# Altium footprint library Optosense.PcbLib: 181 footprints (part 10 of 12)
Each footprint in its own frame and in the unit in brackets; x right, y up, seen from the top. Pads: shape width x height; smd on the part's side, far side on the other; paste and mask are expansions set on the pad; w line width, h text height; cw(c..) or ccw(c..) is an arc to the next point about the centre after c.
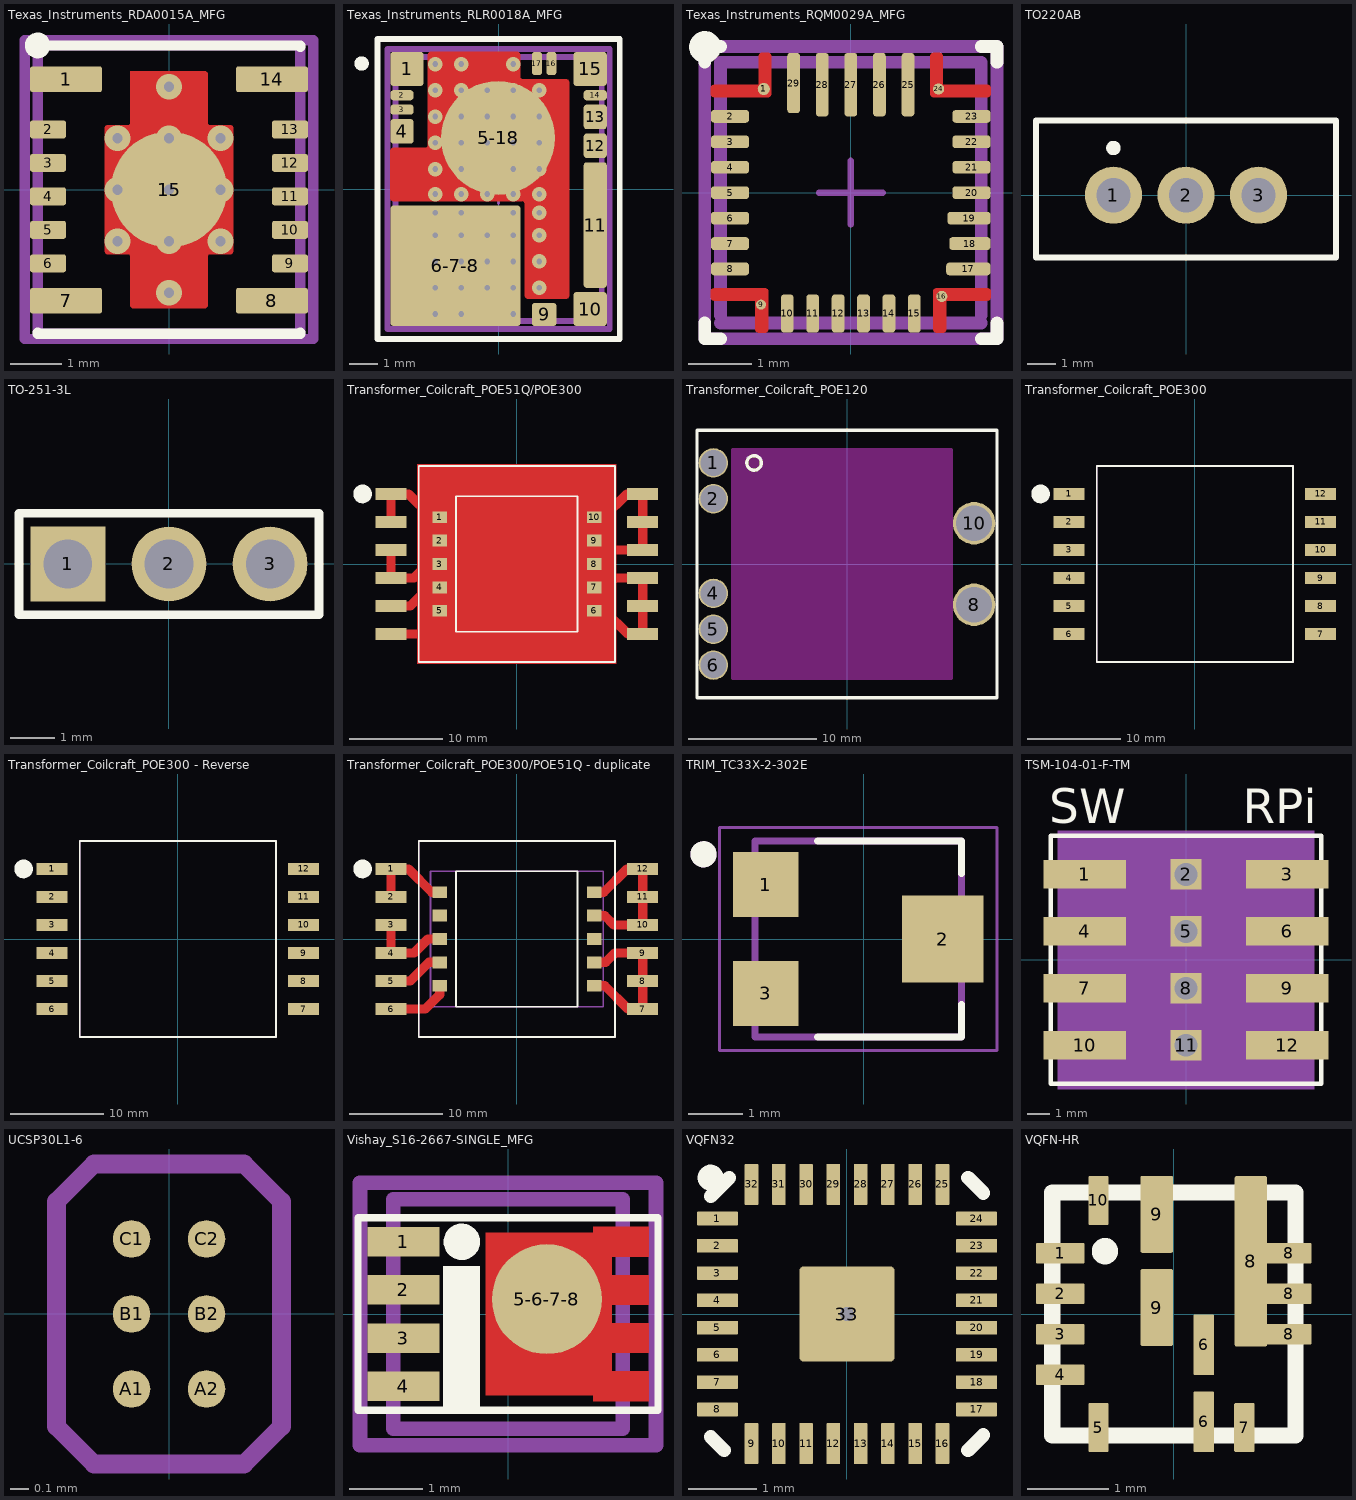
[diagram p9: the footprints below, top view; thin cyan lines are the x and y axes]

## Texas_Instruments_RDA0015A_MFG [mm]
pads (15):
  rrect20% 1.4x0.5 smd paste-1000 mask+0: 1(-2,2.145) 7(-2,-2.155) 8(2,-2.155) 14(2,2.145)
  rrect29% 0.7x0.35 smd paste-1000 mask+0: 2(-2.35,1.17) 3(-2.35,0.52) 4(-2.35,-0.13) 5(-2.35,-0.78) 6(-2.35,-1.43) 9(2.35,-1.43) 10(2.35,-0.78) 11(2.35,-0.13) 12(2.35,0.52) 13(2.35,1.17)
  round 2.25 smd paste-1000 mask+0: 15(0,0)
via 0,2 diameter 0.5 hole 0.2
via 0,1 diameter 0.5 hole 0.2
via 0,0 diameter 0.5 hole 0.2
via 0,-1 diameter 0.5 hole 0.2
via 0,-2 diameter 0.5 hole 0.2
via -1,1 diameter 0.5 hole 0.2
via -1,0 diameter 0.5 hole 0.2
via -1,-1 diameter 0.5 hole 0.2
via 1,1 diameter 0.5 hole 0.2
via 1,0 diameter 0.5 hole 0.2
via 1,-1 diameter 0.5 hole 0.2
Top Layer:
  region: -0.75,2.3 -0.753,2.294 -0.757,2.282 -0.757,2.268 -0.753,2.256 -0.75,2.25 -0.75,1.3 -0.751,1.29 -0.758,1.272 -0.772,1.258 -0.79,1.251 -0.8,1.25 -1.2,1.25 -1.21,1.25 -1.228,1.242 -1.242,1.228 -1.25,1.21 -1.25,1.2 -1.25,-1.2 -1.25,-1.21 -1.242,-1.228 -1.228,-1.242 -1.21,-1.25 -1.2,-1.25 -0.8,-1.25 -0.79,-1.251 -0.772,-1.258 -0.758,-1.272 -0.751,-1.29 -0.75,-1.3 -0.75,-2.25 -0.75,-2.26 -0.742,-2.278 -0.728,-2.292 -0.71,-2.3 -0.7,-2.3 0.7,-2.3 0.71,-2.3 0.728,-2.292 0.742,-2.278 0.75,-2.26 0.75,-2.25 0.75,-1.3 0.751,-1.29 0.758,-1.272 0.772,-1.258 0.79,-1.251 0.8,-1.25 1.2,-1.25 1.21,-1.25 1.228,-1.242 1.242,-1.228 1.25,-1.21 1.25,-1.2 1.25,1.2 1.25,1.21 1.242,1.228 1.228,1.242 1.21,1.25 1.2,1.25 0.8,1.25 0.79,1.251 0.772,1.258 0.758,1.272 0.751,1.29 0.75,1.3 0.75,2.25 0.75,2.26 0.742,2.278 0.728,2.292 0.71,2.3 0.7,2.3
Top Overlay:
  circle w0.25: c-2.551,2.802 r0.125
  lines w0.2: -2.55,-2.78 -2.55,-2.8 2.55,-2.8 2.55,-2.78 ; -2.55,2.77 -2.55,2.8 2.55,2.8 2.55,2.77
Top Paste:
  drawing of 22 lines, arcs and shapes, not listed
Mechanical 10:
  lines w0.2: -2.8,-2.9 2.8,-2.9 2.8,2.9 -2.8,2.9 -2.8,-2.9
  text ".Designator" at 0,0 h1
Mechanical 12:
  lines w0.2: -2.55,-2.8 2.55,-2.8 2.55,2.8 -2.55,2.8 -2.55,-2.8
Mechanical 15:
  lines w0.1: -0.5,0 0.5,0 ; 0,-0.5 0,0.5
  lines w0.2: -2.8,-2.9 2.8,-2.9 2.8,2.9 -2.8,2.9 -2.8,-2.9
3D body "IC_Texas_Instruments_TPSM53604RDAR_eec.STEP": height 0.25, standoff 0, extent -2.8,-2.9 2.8,2.9

## Texas_Instruments_RLR0018A_MFG [mm]
pads (15):
  rrect17% 1.15x1.175 smd paste-1000 mask-1000: 1(-3.176,4.163) 10(3.176,-4.163) 15(3.176,4.163)
  rrect57% 0.8x0.35 smd paste-1000 mask-1000: 2(-3.35,3.25) 3(-3.35,2.75) 14(3.35,3.25)
  rrect25% 0.8x0.85 smd paste-1000 mask-1000: 4(-3.35,2) 12(3.35,1.5) 13(3.35,2.5)
  round 3.952 smd paste-1000 mask-1000: 5-18(-0.021,1.771)
  rrect5% 4.51x4.176 smd paste-1000 mask-1000: 6-7-8(-1.495,-2.663)
  rrect25% 0.85x0.8 smd paste-1000 mask-1000: 9(1.58,-4.35)
  rrect25% 0.8x4.35 smd paste-1000 mask-1000: 11(3.35,-1.25)
  rrect57% 0.35x0.8 smd paste-1000 mask-1000: 16(1.83,4.35) 17(1.33,4.35)
via -2.195,4.33 diameter 0.5 hole 0.2
via -1.295,4.33 diameter 0.5 hole 0.2
via 0.505,4.33 diameter 0.5 hole 0.2
via -2.195,1.6 diameter 0.5 hole 0.2
via -1.295,1.6 diameter 0.5 hole 0.2
via -0.395,1.6 diameter 0.5 hole 0.2
via 0.505,1.6 diameter 0.5 hole 0.2
via 1.405,1.6 diameter 0.5 hole 0.2
via -2.195,0.69 diameter 0.5 hole 0.2
via -1.295,0.69 diameter 0.5 hole 0.2
via 0.505,0.69 diameter 0.5 hole 0.2
via 1.405,0.69 diameter 0.5 hole 0.2
via -2.195,-0.175 diameter 0.5 hole 0.2
via -1.295,-0.175 diameter 0.5 hole 0.2
via -0.395,-0.175 diameter 0.5 hole 0.2
via 0.505,-0.175 diameter 0.5 hole 0.2
via 1.405,-0.175 diameter 0.5 hole 0.2
via -2.195,-0.825 diameter 0.5 hole 0.2
via -1.295,-0.825 diameter 0.5 hole 0.2
via 0.505,-0.825 diameter 0.5 hole 0.2
via 1.405,-0.825 diameter 0.5 hole 0.2
via -2.195,-1.6 diameter 0.5 hole 0.2
via -1.295,-1.6 diameter 0.5 hole 0.2
via -0.395,-1.6 diameter 0.5 hole 0.2
via 0.505,-1.6 diameter 0.5 hole 0.2
via 1.405,-1.6 diameter 0.5 hole 0.2
via -2.195,-2.51 diameter 0.5 hole 0.2
via -1.295,-2.51 diameter 0.5 hole 0.2
via -0.395,-2.51 diameter 0.5 hole 0.2
via 0.505,-2.51 diameter 0.5 hole 0.2
via 1.405,-2.51 diameter 0.5 hole 0.2
via -2.195,-3.42 diameter 0.5 hole 0.2
via -1.295,-3.42 diameter 0.5 hole 0.2
via -0.395,-3.42 diameter 0.5 hole 0.2
via 0.505,-3.42 diameter 0.5 hole 0.2
via 1.405,-3.42 diameter 0.5 hole 0.2
via -2.195,-4.33 diameter 0.5 hole 0.2
via -1.295,-4.33 diameter 0.5 hole 0.2
via 0.505,-4.33 diameter 0.5 hole 0.2
via -2.195,2.51 diameter 0.5 hole 0.2
via -1.295,2.51 diameter 0.5 hole 0.2
via -0.395,2.51 diameter 0.5 hole 0.2
via 0.505,2.51 diameter 0.5 hole 0.2
via 1.405,2.51 diameter 0.5 hole 0.2
via -2.195,3.42 diameter 0.5 hole 0.2
via -1.295,3.42 diameter 0.5 hole 0.2
via -0.395,3.42 diameter 0.5 hole 0.2
via 0.505,3.42 diameter 0.5 hole 0.2
via 1.405,3.42 diameter 0.5 hole 0.2
Top Layer:
  region: -3.651,1.425 -2.551,1.425 -2.531,1.427 -2.495,1.442 -2.467,1.47 -2.452,1.506 -2.451,1.525 -2.45,4.651 -2.45,4.67 -2.435,4.707 -2.407,4.735 -2.37,4.751 -2.35,4.751 -2.351,4.751 0.65,4.751 0.67,4.751 0.707,4.735 0.735,4.707 0.75,4.67 0.75,4.651 0.75,3.9 0.752,3.88 0.767,3.844 0.794,3.817 0.83,3.802 0.85,3.8 2.35,3.8 2.37,3.8 2.407,3.785 2.435,3.757 2.45,3.72 2.45,3.7 2.45,-3.7 2.45,-3.72 2.435,-3.757 2.407,-3.785 2.37,-3.8 2.35,-3.8 1.01,-3.8 0.99,-3.8 0.953,-3.785 0.925,-3.757 0.91,-3.72 0.91,-3.7 0.91,-0.525 0.908,-0.505 0.893,-0.469 0.866,-0.442 0.83,-0.427 0.81,-0.425 -3.65,-0.425 -3.67,-0.425 -3.707,-0.41 -3.735,-0.382 -3.75,-0.345 -3.75,-0.325 -3.751,-0.325 -3.75,1.325 -3.75,1.345 -3.735,1.382 -3.707,1.41 -3.67,1.425
Top Overlay:
  circle w0.25: c-4.75,4.351 r0.125
  lines w0.2: -4.2,-5.2 4.2,-5.2 4.2,5.2 -4.2,5.2 -4.2,-5.2
Top Paste:
  drawing of 46 lines, arcs and shapes, not listed
Top Solder:
  drawing of 18 lines, arcs and shapes, not listed
Mechanical 10:
  lines w0.2: -3.851,-4.851 3.851,-4.851 3.851,4.851 -3.851,4.851 -3.851,-4.851
  text ".Designator" at 0,0 h1
Mechanical 12:
  lines w0.2: -3.575,-4.575 3.575,-4.575 3.575,4.575 -3.575,4.575 -3.575,-4.575
Mechanical 15:
  lines w0.1: -0.5,0 0.5,0 ; 0,-0.5 0,0.5
  lines w0.2: -3.851,-4.851 3.851,-4.851 3.851,4.851 -3.851,4.851 -3.851,-4.851
3D body "IC_Texas_Instruments_LMZM33603RLRR_eec.STEP": height 0.25, standoff 0, extent -3.851,-4.851 3.851,4.851

## Texas_Instruments_RQM0029A_MFG [mm]
pads (29):
  round 0.192 smd paste-0.025 mask+0: 1(-1.369,1.631)
  rrect50% 0.6x0.2 smd paste-0.025 mask+0: 2(-1.9,1.2) 3(-1.9,0.8) 4(-1.9,0.4) 5(-1.9,0) 6(-1.9,-0.4) 7(-1.9,-0.8) 8(-1.9,-1.2) 20(1.9,0) 21(1.9,0.4) 22(1.9,0.8) 23(1.9,1.2)
  round 0.158 smd paste-0.025 mask+0: 9(-1.412,-1.763)
  rrect50% 0.2x0.6 smd paste-0.025 mask+0: 10(-1,-1.9) 11(-0.6,-1.9) 12(-0.2,-1.9) 13(0.2,-1.9) 14(0.6,-1.9) 15(1,-1.9)
  round 0.175 smd paste-0.025 mask+0: 16(1.431,-1.631) 24(1.381,1.631)
  rrect50% 0.7x0.2 smd paste-0.025 mask+0: 17(1.85,-1.2)
  rrect50% 0.65x0.2 smd paste-0.025 mask+0: 18(1.875,-0.8)
  rrect50% 0.68x0.2 smd paste-0.025 mask+0: 19(1.86,-0.4)
  rrect50% 0.2x1 smd paste-0.025 mask+0: 25(0.9,1.7) 26(0.45,1.7) 27(0,1.7) 28(-0.45,1.7)
  rrect50% 0.2x0.95 smd paste-0.025 mask+0: 29(-0.9,1.725)
Top Layer:
  region: 2.2,1.65 2.2,1.66 2.192,1.678 2.178,1.692 2.16,1.7 2.15,1.7 1.45,1.7 1.45,2.15 1.45,2.16 1.442,2.178 1.428,2.192 1.41,2.2 1.4,2.2 1.3,2.2 1.29,2.2 1.272,2.192 1.258,2.178 1.25,2.16 1.25,2.15 1.25,1.55 1.25,1.54 1.258,1.522 1.272,1.508 1.29,1.5 1.3,1.5 2.15,1.5 2.16,1.5 2.178,1.508 2.192,1.522 2.2,1.54 2.2,1.55
  region: 2.2,-1.65 2.2,-1.66 2.192,-1.678 2.178,-1.692 2.16,-1.7 2.15,-1.7 1.5,-1.7 1.5,-2.15 1.5,-2.16 1.492,-2.178 1.478,-2.192 1.46,-2.2 1.45,-2.2 1.35,-2.2 1.34,-2.2 1.322,-2.192 1.308,-2.178 1.3,-2.16 1.3,-2.15 1.3,-1.55 1.3,-1.54 1.308,-1.522 1.322,-1.508 1.34,-1.5 1.35,-1.5 2.15,-1.5 2.16,-1.5 2.178,-1.508 2.192,-1.522 2.2,-1.54 2.2,-1.55
  region: -2.2,-1.65 -2.2,-1.66 -2.192,-1.678 -2.178,-1.692 -2.16,-1.7 -2.15,-1.7 -1.5,-1.7 -1.5,-2.15 -1.5,-2.16 -1.492,-2.178 -1.478,-2.192 -1.46,-2.2 -1.45,-2.2 -1.35,-2.2 -1.34,-2.2 -1.322,-2.192 -1.308,-2.178 -1.3,-2.16 -1.3,-2.15 -1.3,-1.55 -1.3,-1.54 -1.308,-1.522 -1.322,-1.508 -1.34,-1.5 -1.35,-1.5 -2.15,-1.5 -2.16,-1.5 -2.178,-1.508 -2.192,-1.522 -2.2,-1.54 -2.2,-1.55
  region: -2.2,1.65 -2.2,1.66 -2.192,1.678 -2.178,1.692 -2.16,1.7 -2.15,1.7 -1.45,1.7 -1.45,2.15 -1.45,2.16 -1.442,2.178 -1.428,2.192 -1.41,2.2 -1.4,2.2 -1.3,2.2 -1.29,2.2 -1.272,2.192 -1.258,2.178 -1.25,2.16 -1.25,2.15 -1.25,1.55 -1.25,1.54 -1.258,1.522 -1.272,1.508 -1.29,1.5 -1.3,1.5 -2.15,1.5 -2.16,1.5 -2.178,1.508 -2.192,1.522 -2.2,1.54 -2.2,1.55
Top Overlay:
  circle w0.25: c-2.295,2.291 r0.125
  lines w0.2: -2.3,-2.05 -2.3,-2.3 -2.05,-2.3 ; -2.3,2.05 -2.3,2.3 -2.05,2.3 ; 2.05,-2.3 2.3,-2.3 2.3,-2.05 ; 2.05,2.3 2.3,2.3 2.3,2.05
Mechanical 10:
  lines w0.2: -2.3,-2.3 -2.3,2.3 2.3,2.3 2.3,-2.3 -2.3,-2.3
  text ".Designator" at 0,0.188 h1
Mechanical 12:
  lines w0.2: -2.05,-2.05 2.05,-2.05 ; -2.05,-1.93 -2.05,2.05 2.05,2.05 2.05,-1.93
Mechanical 15:
  lines w0.1: -0.5,0 0.5,0 ; 0,-0.5 0,0.5
  lines w0.2: -2.3,-2.3 -2.3,2.3 2.3,2.3 2.3,-2.3 -2.3,-2.3
3D body "IC_Texas_Instruments_BQ25792RQMR_eec.STEP": height 0.25, standoff 0, extent -2.3,-2.3 2.3,2.3

## TO220AB [mm]
height 19.6
pads (3):
  round 2 hole 1.2: 1(-2.54,0) 2(0,0) 3(2.54,0)
Top Overlay:
  circle w0.254: c-2.54,1.65 r0.125
  lines w0.2: -5.25,-2.184 5.25,-2.184 5.25,2.616 -5.25,2.616 -5.25,-2.184
3D body "User Library-TO-220AB.STEP": height 20.86, standoff -3, extent -5.31,-2.214 5.36,2.616

## TO-251-3L [mm]
pads (3):
  rect 1.7x1.7 hole 1.1: 1(-2.29,0)
  round 1.7 hole 1.1: 2(0,0) 3(2.29,0)
Top Overlay:
  lines w0.2: -3.4,-1.15 -3.4,1.15 3.4,1.15 3.4,-1.15 -3.4,-1.15

## Transformer_Coilcraft_POE51Q/POE300 [mm] "POE300F-24L"
height 9.652
pads (23):
  rect 1.55x1.27 smd: 1(-8.268,5) 2(-8.268,2.5) 3(-8.268,0) 4(-8.268,-2.5) 5(-8.268,-5) 6(8.268,-5) 7(8.268,-2.5) 8(8.268,0) 9(8.268,2.5) 10(8.268,5)
  rect 3.3x1.27 smd: ""(-13.46,-7.5) ""(-13.46,-4.5) ""(-13.46,-1.5) ""(-13.46,1.5) ""(-13.46,4.5) ""(-13.46,7.5) ""(-13.46,7.5) ""(13.46,-7.5) ""(13.46,-4.5) ""(13.46,-1.5) ""(13.46,1.5) ""(13.46,4.5) ""(13.46,7.5)
Top Layer:
  pour cut-out: -10.668,10.668 -10.668,-10.668 10.668,-10.668 10.668,10.668
  lines w0.254: -13.46,4.5 -13.46,7.5 -11.3,7.5 -8.8,5 ; -9.1,5 -8.268,5 ; 8.268,5 8.8,5
  lines w1: -13.46,-7.5 -9.8,-7.5 -8.268,-5.968 -8.268,-5 ; -13.46,-4.5 -11.4,-4.5 -9.4,-2.5 -8.268,-2.5 ; -13.46,1.5 -13.46,-1.5 -11,-1.5 -9.5,0 -8.268,0 ; -13.46,4.5 -13.46,7.5 -11.6,7.5 -9.1,5 ; 8.268,-5 9.4,-5 11.9,-7.5 13.46,-7.5 13.46,-1.5 10.5,-1.5 9.5,-2.5 8.268,-2.5 ; 8.268,2.5 9.4,2.5 10.4,1.5 13.46,1.5 13.46,7.5 11.8,7.5 9.3,5 8.268,5
Top Overlay:
  circle w1: c-16.5,7.5 r0.5
  lines w0.2: -10.5,-10.5 10.5,-10.5 10.5,10.5 -10.5,10.5 -10.5,-10.5 ; -6.5,-7.25 -6.5,7.25 6.5,7.25 6.5,-7.25 -6.5,-7.25
Mechanical 15:
  lines w0.2: -10.5,-10.5 10.5,-10.5 10.5,10.5 -10.5,10.5 -10.5,-10.5 ; -9.25,-7.25 9.25,-7.25 9.25,7.25 -9.25,7.25 -9.25,-7.25
3D body "Coilcraft-POE51Q-XXX.STEP": height 13.87, standoff 0, extent -8.5,-7.25 8.5,7.25

## Transformer_Coilcraft_POE120 [mil] "POE12PL-24"
height 380
pads (7):
  round 90 hole 80: 1(-410,310) 2(-410,200) 4(-410,-90) 5(-410,-200) 6(-410,-310)
  round 130 hole 110: 8(390,-125) 10(390,125)
Top Overlay:
  circle w10: c-285,310 r22.29
  lines w10: -460,-410 460,-410 460,410 -460,410 -460,-410
Keep-Out Layer:
  region: -350,350 -350,-350 320,-350 320,350
  lines w10: 320,345 320,-350 -350,-350 -350,350 320,350
3D body "Coilcraft-POE120PL-12L.STEP": height 342.95, standoff -8.82, extent -460.04,-410.04 460.04,410.04

## Transformer_Coilcraft_POE300 [mm] "POE300F-24L"
height 9.652
pads (13):
  rect 3.3x1.27 smd: 1(-13.46,7.5) 1(-13.46,7.5) 2(-13.46,4.5) 3(-13.46,1.5) 4(-13.46,-1.5) 5(-13.46,-4.5) 6(-13.46,-7.5) 7(13.46,-7.5) 8(13.46,-4.5) 9(13.46,-1.5) 10(13.46,1.5) 11(13.46,4.5) 12(13.46,7.5)
Top Overlay:
  circle w1: c-16.5,7.5 r0.5
  lines w0.2: -10.5,-10.5 10.5,-10.5 10.5,10.5 -10.5,10.5 -10.5,-10.5
Mechanical 15:
  lines w0.2: -10.5,-10.5 10.5,-10.5 10.5,10.5 -10.5,10.5 -10.5,-10.5
3D body "Coilcraft-POE300F-XXX.step": height 11.38, standoff -0.05, extent -14.325,-10.285 14.325,10.285

## Transformer_Coilcraft_POE300 - Reverse [mm] "POE300F-24L"
height 9.652
pads (13):
  rect 3.3x1.27 smd: 1(-13.46,7.5) 1(-13.46,7.5) 2(-13.46,4.5) 3(-13.46,1.5) 4(-13.46,-1.5) 5(-13.46,-4.5) 6(-13.46,-7.5) 7(13.46,-7.5) 8(13.46,-4.5) 9(13.46,-1.5) 10(13.46,1.5) 11(13.46,4.5) 12(13.46,7.5)
Top Overlay:
  circle w1: c-16.5,7.5 r0.5
  lines w0.2: -10.5,-10.5 -10.5,10.5 10.5,10.5 10.5,-10.5 -10.5,-10.5
Mechanical 15:
  lines w0.2: -10.5,-10.5 -10.5,10.5 10.5,10.5 10.5,-10.5 -10.5,-10.5
3D body "Coilcraft-POE300F-XXX.step": height 0.45, standoff -10.98, extent -14.325,-10.285 14.325,10.285

## Transformer_Coilcraft_POE300/POE51Q - duplicate [mm] "POE300F-24L"
height 9.652
pads (23):
  rect 3.3x1.27 smd: 1(-13.46,7.5) 1(-13.46,7.5) 2(-13.46,4.5) 3(-13.46,1.5) 4(-13.46,-1.5) 5(-13.46,-4.5) 6(-13.46,-7.5) 7(13.46,-7.5) 8(13.46,-4.5) 9(13.46,-1.5) 10(13.46,1.5) 11(13.46,4.5) 12(13.46,7.5)
  rect 1.55x1.27 smd: ""(-8.268,-5) ""(-8.268,-2.5) ""(-8.268,0) ""(-8.268,2.5) ""(-8.268,5) ""(8.268,-5) ""(8.268,-2.5) ""(8.268,0) ""(8.268,2.5) ""(8.268,5)
Top Layer:
  lines w0.254: -13.46,4.5 -13.46,7.5 -11.3,7.5 -8.8,5 ; -9.1,5 -8.268,5 ; 8.268,5 8.8,5
  lines w1: -13.46,-7.5 -9.8,-7.5 -8.268,-5.968 -8.268,-5 ; -13.46,-4.5 -11.4,-4.5 -9.4,-2.5 -8.268,-2.5 ; -13.46,1.5 -13.46,-1.5 -11,-1.5 -9.5,0 -8.268,0 ; -13.46,4.5 -13.46,7.5 -11.6,7.5 -9.1,5 ; 8.268,-5 9.4,-5 11.9,-7.5 13.46,-7.5 13.46,-1.5 10.5,-1.5 9.5,-2.5 8.268,-2.5 ; 8.268,2.5 9.4,2.5 10.4,1.5 13.46,1.5 13.46,7.5 11.8,7.5 9.3,5 8.268,5
Top Overlay:
  circle w1: c-16.5,7.5 r0.5
  lines w0.2: -10.5,-10.5 -10.5,10.5 10.5,10.5 10.5,-10.5 -10.5,-10.5 ; -6.5,-7.25 6.5,-7.25 6.5,7.25 -6.5,7.25 -6.5,-7.25
Mechanical 15:
  lines w0.2: -10.5,-10.5 -10.5,10.5 10.5,10.5 10.5,-10.5 -10.5,-10.5 ; -9.25,-7.25 -9.25,7.25 9.25,7.25 9.25,-7.25 -9.25,-7.25
3D body "Coilcraft-POE300F-XXX.step": height 11.38, standoff -0.05, extent -14.325,-10.285 14.325,10.285

## TRIM_TC33X-2-302E [mm]
pads (3):
  rect 1.2x1.2 smd: 1(-1.8,1) 3(-1.8,-1)
  rect 1.5x1.6 smd: 2(1.45,0)
Top Overlay:
  circle w0.24: c-2.946,1.558 r0.12
  lines w0.127: -0.85,-1.8 1.8,-1.8 1.8,-1.2 ; -0.85,1.8 1.8,1.8 1.8,1.2
Mechanical 13:
  circle w0.24: c-2.946,1.558 r0.12
  lines w0.127: -2,-1.8 -2,1.8 1.8,1.8 1.8,-1.8 -2,-1.8
Mechanical 15:
  lines w0.05: -2.65,-2.05 -2.65,2.05 2.45,2.05 2.45,-2.05 -2.65,-2.05
3D body "step_temp.STEP": height 1.1, standoff -0.1, extent -1.9,-1.5 1.9,1.5

## TSM-104-01-F-TM [mm] "TSM-104-01-F-TM"
pads (12):
  rect 3.68x1.27 smd mask+0: 1(-4.508,3.81) 3(4.508,3.81) 4(-4.508,1.27) 6(4.508,1.27) 7(-4.508,-1.27) 9(4.508,-1.27) 10(-4.508,-3.81) 12(4.508,-3.81)
  rect 1.37x1.37 hole 1.02: 2(0,3.81) 5(0,1.27) 8(0,-1.27) 11(0,-3.81)
Top Overlay:
  lines w0.2: -6.038,-0.45 -6.038,5.53 6.038,5.53 6.038,-0.45 ; -6.038,0.45 -6.038,-5.53 6.038,-5.53 6.038,0.45
  text "RPi" at 2.54,6.096 h1.52
  text "SW" at -6.096,6.096 h1.52
Top Paste:
  region: -6.348,3.175 -6.348,4.445 -2.668,4.445 -2.668,3.175
  region: 6.348,3.175 6.348,4.445 2.668,4.445 2.668,3.175
  region: 6.348,0.635 6.348,1.905 2.668,1.905 2.668,0.635
  region: -6.348,0.635 -6.348,1.905 -2.668,1.905 -2.668,0.635
  region: 6.348,-1.905 6.348,-0.635 2.668,-0.635 2.668,-1.905
  region: -6.348,-1.905 -6.348,-0.635 -2.668,-0.635 -2.668,-1.905
  region: 6.348,-4.445 6.348,-3.175 2.668,-3.175 2.668,-4.445
  region: -6.348,-4.445 -6.348,-3.175 -2.668,-3.175 -2.668,-4.445
Top Solder:
  region: -6.399,3.124 -6.399,4.496 -2.617,4.496 -2.617,3.124
  region: 6.399,3.124 6.399,4.496 2.617,4.496 2.617,3.124
  region: 6.399,0.584 6.399,1.956 2.617,1.956 2.617,0.584
  region: -6.399,0.584 -6.399,1.956 -2.617,1.956 -2.617,0.584
  region: 6.399,-1.956 6.399,-0.584 2.617,-0.584 2.617,-1.956
  region: -6.399,-1.956 -6.399,-0.584 -2.617,-0.584 -2.617,-1.956
  region: 6.399,-4.496 6.399,-3.124 2.617,-3.124 2.617,-4.496
  region: -6.399,-4.496 -6.399,-3.124 -2.617,-3.124 -2.617,-4.496
Mechanical 13:
  drawing of 151 lines, arcs and shapes, not listed
Mechanical 15:
  region: -5.715,-0.685 -5.715,5.765 5.715,5.765 5.715,-0.685
  region: -5.715,-5.765 -5.715,0.685 5.715,0.685 5.715,-5.765
3D body "TSM-104-01-F-TM.stp": height 9.65, standoff -2.54, extent -5.715,-5.08 5.715,5.08

## UCSP30L1-6 [mm]
pads (6):
  round 0.2 smd: A1(-0.2,-0.4) A2(0.2,-0.4) B1(-0.2,0) B2(0.2,0) C1(-0.2,0.4) C2(0.2,0.4)
Mechanical 1:
  lines w0.1: -0.6,-0.6 -0.6,0.6 -0.4,0.8 0.4,0.8 0.6,0.6 0.6,-0.6 0.4,-0.8 -0.4,-0.8 -0.6,-0.6

## Vishay_S16-2667-SINGLE_MFG [mil]
pads (5):
  rect 39x16 smd paste+0 mask+0: 1(-56.5,39) 2(-56.5,13) 3(-56.5,-13) 4(-56.5,-39)
  round 59.4 smd paste+0 mask+0: 5-6-7-8(21,8)
Top Layer:
  region: -12,44 46,44 46,47 76,47 76,31 56,31 56,21 76,21 76,5 56,5 56,-5 76,-5 76,-21 56,-21 56,-31 76,-31 76,-47 46,-47 46,-44 -12,-44
Top Overlay:
  circle w9.84: c-25,39 r4.92
  rectangle: -35,-52 -15,26
  lines w3.94: -81,-52 81,-52 81,52 -81,52 -81,-52
Mechanical 10:
  lines w7.87: -79.94,-70.87 79.94,-70.87 79.94,70.87 -79.94,70.87 -79.94,-70.87
Mechanical 12:
  lines w7.87: -62.01,-62.01 62.01,-62.01 62.01,62.01 -62.01,62.01 -62.01,-62.01
Mechanical 15:
  lines w3.94: 0,-19.68 0,19.68
  lines w7.87: -79.94,-70.87 79.94,-70.87 79.94,70.87 -79.94,70.87 -79.94,-70.87
3D body "Trans_Vishay_SI7322ADN-T1-GE3_eec.STEP": height 10, standoff 0, extent -79.94,-70.87 79.94,70.87

## VQFN32 [mm]
height 1
pads (33):
  rrect10% 0.6x0.2 smd paste-0.025 mask+0.05: 1(-1.9,1.4) 2(-1.9,1) 3(-1.9,0.6) 4(-1.9,0.2) 5(-1.9,-0.2) 6(-1.9,-0.6) 7(-1.9,-1) 8(-1.9,-1.4) 17(1.9,-1.4) 18(1.9,-1) 19(1.9,-0.6) 20(1.9,-0.2) 21(1.9,0.2) 22(1.9,0.6) 23(1.9,1) 24(1.9,1.4)
  rrect10% 0.2x0.6 smd paste-0.025 mask+0.05: 9(-1.4,-1.9) 10(-1,-1.9) 11(-0.6,-1.9) 12(-0.2,-1.9) 13(0.2,-1.9) 14(0.6,-1.9) 15(1,-1.9) 16(1.4,-1.9) 25(1.4,1.9) 26(1,1.9) 27(0.6,1.9) 28(0.2,1.9) 29(-0.2,1.9) 30(-0.6,1.9) 31(-1,1.9) 32(-1.4,1.9)
  rrect10% 1.4x1.4 smd paste-0.025 mask+0.05: 33(0,0)
via 0,0 diameter 0.4 hole 0.2
Top Overlay:
  circle w0.2: c-2,2 r0.09
  lines w0.2: -2,-1.8 -1.8,-2 ; -2,1.725 -1.725,2 ; 1.775,-2 2,-1.775 ; 1.775,2 2,1.775
3D body: height 0.8, standoff 0, extent -2.083,-2.083 2.083,2.083

## VQFN-HR [mm]
height 1
pads (15):
  rrect10% 0.6x0.25 smd mask+0.07: 1(-1.4,0.75) 2(-1.4,0.25) 3(-1.4,-0.25) 4(-1.4,-0.75)
  rrect10% 0.25x0.6 smd mask+0.07: 5(-0.93,-1.4) 7(0.87,-1.4) 10(-0.93,1.4)
  rrect10% 0.25x0.75 smd mask+0.07: 6(0.37,-1.33) 6(0.37,-0.38)
  rrect10% 0.4x2.1 smd mask+0.07: 8(0.95,0.65)
  rrect10% 0.56x0.25 smd mask+0.07: 8(1.42,-0.25) 8(1.42,0.25) 8(1.42,0.75)
  rrect10% 0.4x0.95 smd mask+0.07: 9(-0.21,0.08) 9(-0.21,1.23)
Top Overlay:
  circle w0.254: c-0.85,0.775 r0.035
  lines w0.2: -1.5,-1.5 1.5,-1.5 1.5,1.5 -1.5,1.5 -1.5,-1.5
3D body: height 0.55, standoff 0.05, extent -1.4,-1.4 1.4,1.4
